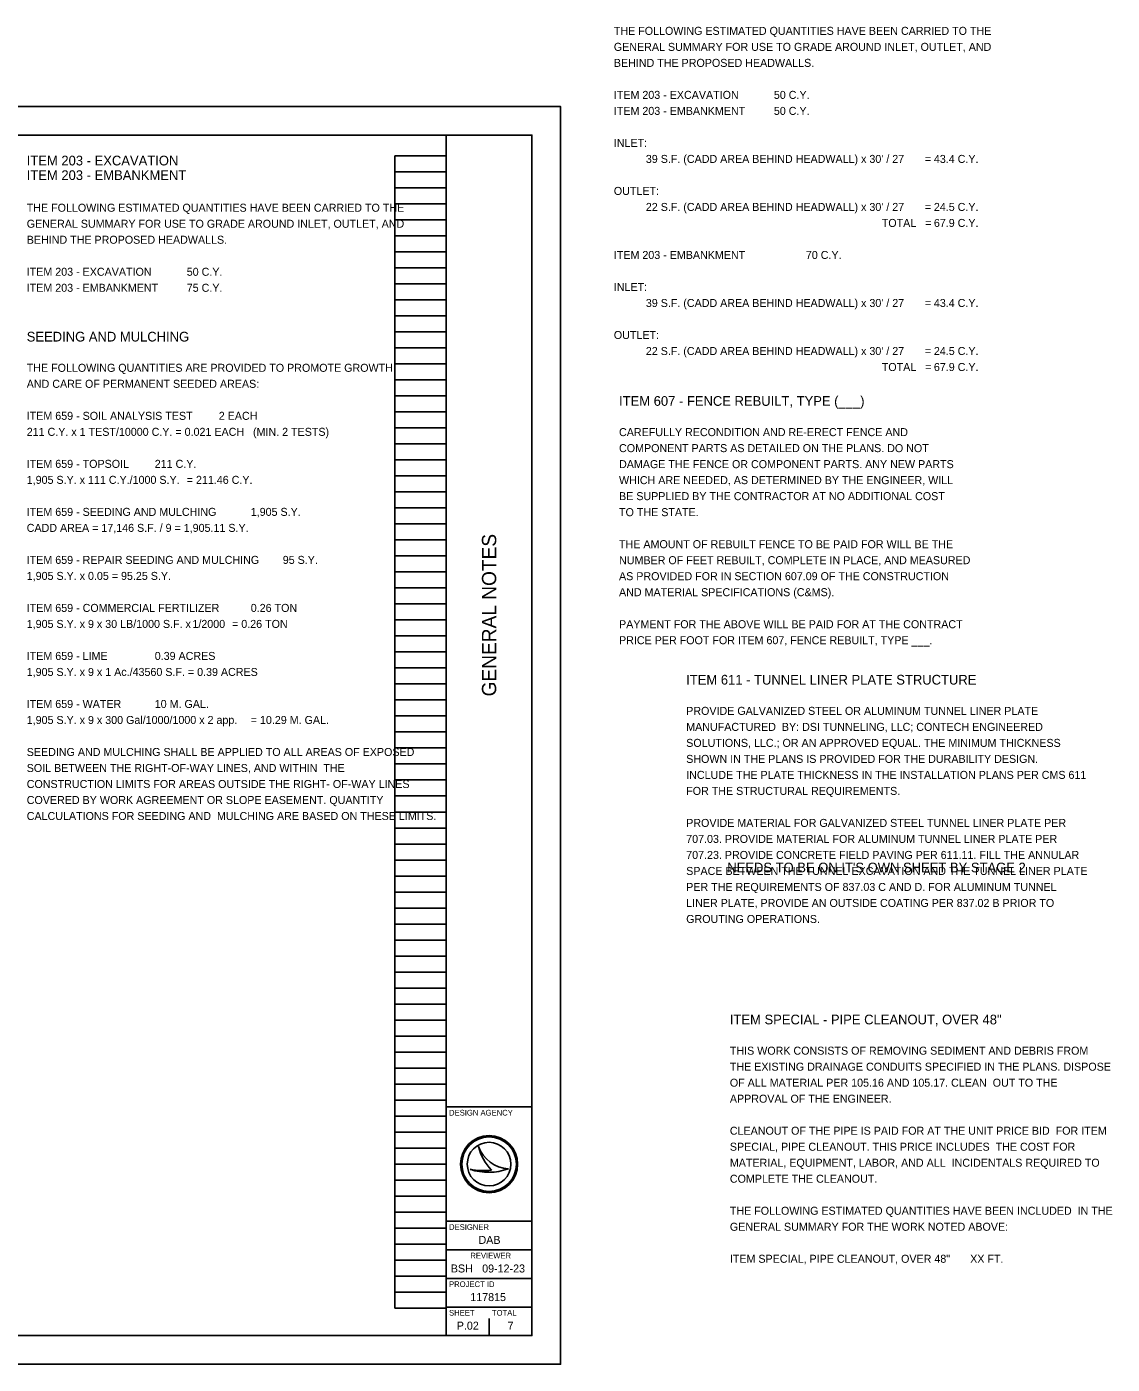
# Model space of a CAD drawing. Extents: x -3.4 to 43.7, y 0 to 26.
# Drawn here: x 24.66 to 43.65, y 0 to 23.4 of the extents above; entities that cross this region are included whole.
import ezdxf

# ---------------------------------------------------------------- set-up
doc = ezdxf.new("R2010")
doc.units = 0
for name, color, linetype in [('SH_Border', 7, 'Continuous'), ('SH_Cut_Line', 7, 'Continuous'), ('SH_Data', 7, 'Continuous'), ('SH_Text', 7, 'Continuous')]:
    doc.layers.add(name, color=color, linetype=linetype)

msp = doc.modelspace()

# ---------------------------------------------------------------- linework, layer by layer
at = {"layer": 'SH_Border'}
for p, q in [((32, 0.5), (32, 21.5)), ((32, 4.5), (33.5, 4.5)), ((32, 2.5), (33.5, 2.5)), ((32, 2), (33.5, 2)), ((32, 1.5), (33.5, 1.5)), ((32, 1), (33.5, 1))]:
    msp.add_line(p, q, dxfattribs=at)
msp.add_lwpolyline([(1.5, 21.5), (33.5, 21.5), (33.5, 0.5), (1.5, 0.5)], close=True, dxfattribs=at)
at = {"layer": 'SH_Cut_Line'}
msp.add_lwpolyline([(0, 0), (34, 0), (34, 22), (0, 22)], close=True, dxfattribs=at)
at = {"layer": 'SH_Data'}
for p, q in [((31.1, 0.98), (31.1, 21.14)), ((31.1, 21.14), (32, 21.14)), ((32, 0.98), (32, 21.14)), ((31.1, 20.86), (32, 20.86)), ((31.1, 20.58), (32, 20.58)), ((31.1, 20.3), (32, 20.3)), ((31.1, 20.02), (32, 20.02)), ((31.1, 19.74), (32, 19.74)), ((31.1, 19.46), (32, 19.46)), ((31.1, 19.18), (32, 19.18)), ((31.1, 18.9), (32, 18.9)), ((31.1, 18.62), (32, 18.62)), ((31.1, 18.34), (32, 18.34)), ((31.1, 18.06), (32, 18.06)), ((31.1, 17.78), (32, 17.78)), ((31.1, 17.5), (32, 17.5)), ((31.1, 17.22), (32, 17.22)), ((31.1, 16.94), (32, 16.94)), ((31.1, 16.66), (32, 16.66)), ((31.1, 16.38), (32, 16.38)), ((31.1, 16.1), (32, 16.1)), ((31.1, 15.82), (32, 15.82)), ((31.1, 15.54), (32, 15.54)), ((31.1, 15.26), (32, 15.26)), ((31.1, 14.98), (32, 14.98)), ((31.1, 14.7), (32, 14.7)), ((31.1, 14.42), (32, 14.42)), ((31.1, 14.14), (32, 14.14)), ((31.1, 13.86), (32, 13.86)), ((31.1, 13.58), (32, 13.58)), ((31.1, 13.3), (32, 13.3)), ((31.1, 13.02), (32, 13.02)), ((31.1, 12.74), (32, 12.74)), ((31.1, 12.46), (32, 12.46)), ((31.1, 12.18), (32, 12.18)), ((31.1, 11.9), (32, 11.9)), ((31.1, 11.62), (32, 11.62)), ((31.1, 11.34), (32, 11.34)), ((31.1, 11.06), (32, 11.06)), ((31.1, 10.78), (32, 10.78)), ((31.1, 10.5), (32, 10.5)), ((31.1, 10.22), (32, 10.22)), ((31.1, 9.94), (32, 9.94)), ((31.1, 9.66), (32, 9.66)), ((31.1, 9.38), (32, 9.38)), ((31.1, 9.1), (32, 9.1)), ((31.1, 8.82), (32, 8.82)), ((31.1, 8.54), (32, 8.54)), ((31.1, 8.26), (32, 8.26)), ((31.1, 7.98), (32, 7.98)), ((31.1, 7.7), (32, 7.7)), ((31.1, 7.42), (32, 7.42)), ((31.1, 7.14), (32, 7.14)), ((31.1, 6.86), (32, 6.86)), ((31.1, 6.58), (32, 6.58)), ((31.1, 6.3), (32, 6.3)), ((31.1, 6.02), (32, 6.02)), ((31.1, 5.74), (32, 5.74)), ((31.1, 5.46), (32, 5.46)), ((31.1, 5.18), (32, 5.18)), ((31.1, 4.9), (32, 4.9)), ((31.1, 4.62), (32, 4.62)), ((31.1, 4.34), (32, 4.34)), ((31.1, 4.06), (32, 4.06)), ((31.1, 3.78), (32, 3.78)), ((32.567, 3.81), (32.567, 3.81)), ((31.1, 3.5), (32, 3.5)), ((32.417, 3.41), (32.417, 3.41)), ((32.75, 3.5), (32.75, 3.5)), ((33.087, 3.419), (33.087, 3.419)), ((31.1, 3.22), (32, 3.22)), ((31.1, 2.94), (32, 2.94)), ((31.1, 2.66), (32, 2.66)), ((31.1, 2.38), (32, 2.38)), ((31.1, 2.1), (32, 2.1)), ((31.1, 1.82), (32, 1.82)), ((31.1, 1.54), (32, 1.54)), ((31.1, 1.26), (32, 1.26)), ((31.1, 0.98), (32, 0.98)), ((32.75, 0.5), (32.75, 0.8)), ((32.375, 0.675), (32.375, 0.675))]:
    msp.add_line(p, q, dxfattribs=at)
for radius in [0.5, 0.477, 0.477, 0.382]:
    msp.add_circle((32.75, 3.5), radius, dxfattribs=at)
for centre, radius, start, end in [((33.116, 3.998), 0.58, 198.9257, 198.9319), ((33.347, 3.97), 0.796, 191.6379, 191.6421), ((33.116, 3.998), 0.58, 198.9319, 267.1657), ((33.347, 3.97), 0.796, 191.6421, 226.0947), ((32.739, 4.37), 1.013, 251.4576, 290.0832), ((32.648, 4.654), 1.266, 259.4964, 259.4995), ((32.739, 4.37), 1.013, 251.4527, 251.4576), ((32.648, 4.654), 1.266, 259.4995, 276.6672)]:
    msp.add_arc(centre, radius, start, end, dxfattribs=at)

# ---------------------------------------------------------------- texts
for s, height, p in [('ITEM 659 - SOIL ANALYSIS TEST', 0.14, (24.66, 16.52)), ('2 EACH', 0.14, (28.02, 16.52)), ('211 C.Y. x 1 TEST/10000 C.Y. = 0.021 EACH   (MIN. 2 TESTS)', 0.14, (24.66, 16.24)), ('ITEM 659 - TOPSOIL', 0.14, (24.66, 15.68)), ('211 C.Y.', 0.14, (26.9, 15.68)), ('1,905 S.Y. x 111 C.Y./1000 S.Y.', 0.14, (24.66, 15.4)), ('= 211.46 C.Y.', 0.14, (27.46, 15.4)), ('ITEM 659 - SEEDING AND MULCHING', 0.14, (24.66, 14.84)), ('1,905 S.Y.', 0.14, (28.58, 14.84)), ('CADD AREA = 17,146 S.F. / 9 = 1,905.11 S.Y.', 0.14, (24.66, 14.56)), ('ITEM 659 - REPAIR SEEDING AND MULCHING', 0.14, (24.66, 14)), ('95 S.Y.', 0.14, (29.14, 14)), ('1,905 S.Y. x 0.05 = 95.25 S.Y.', 0.14, (24.66, 13.72)), ('ITEM 659 - COMMERCIAL FERTILIZER', 0.14, (24.66, 13.16)), ('0.26 TON', 0.14, (28.58, 13.16)), ('1,905 S.Y. x 9 x 30 LB/1000 S.F. x', 0.14, (24.66, 12.88)), ('1/2000 ', 0.14, (27.559, 12.88)), ('= 0.26 TON', 0.14, (28.253, 12.88)), ('ITEM 659 - LIME', 0.14, (24.66, 12.32)), ('0.39 ACRES', 0.14, (26.9, 12.32)), ('1,905 S.Y. x 9 x 1 Ac./43560 S.F. = 0.39 ACRES', 0.14, (24.66, 12.04)), ('ITEM 659 - WATER', 0.14, (24.66, 11.48)), ('10 M. GAL.', 0.14, (26.9, 11.48)), ('1,905 S.Y. x 9 x 300 Gal/1000/1000 x 2 app.', 0.14, (24.66, 11.2)), ('= 10.29 M. GAL.', 0.14, (28.58, 11.2)), ('DESIGN AGENCY', 0.1, (32.05, 4.35)), ('DESIGNER', 0.1, (32.05, 2.35)), ('DAB', 0.14, (32.565, 2.105)), ('REVIEWER', 0.1, (32.422, 1.85)), ('BSH', 0.14, (32.08, 1.605)), ('09-12-23', 0.14, (32.629, 1.605)), ('PROJECT ID', 0.1, (32.05, 1.35)), ('117815', 0.14, (32.421, 1.105)), ('SHEET', 0.1, (32.05, 0.85)), ('TOTAL', 0.1, (32.8, 0.85)), ('P.02', 0.14, (32.185, 0.605)), ('7', 0.14, (33.074, 0.605))]:
    msp.add_text(s, height=height, dxfattribs=at).set_placement(p)
msp.add_text('GENERAL NOTES', height=0.25, rotation=90, dxfattribs=at).set_placement((32.875, 11.682))
at = {"layer": 'SH_Text'}
for s, height, p in [('THE FOLLOWING ESTIMATED QUANTITIES HAVE BEEN CARRIED TO THE ', 0.14, (34.933, 23.254)), ('GENERAL SUMMARY FOR USE TO GRADE AROUND INLET, OUTLET, AND ', 0.14, (34.933, 22.974)), ('BEHIND THE PROPOSED HEADWALLS.', 0.14, (34.933, 22.694)), ('ITEM 203 - EXCAVATION', 0.14, (34.933, 22.134)), ('50 C.Y.', 0.14, (37.733, 22.134)), ('ITEM 203 - EMBANKMENT', 0.14, (34.933, 21.854)), ('50 C.Y.', 0.14, (37.733, 21.854)), ('INLET:', 0.14, (34.933, 21.294)), ('ITEM 203 - EXCAVATION', 0.17, (24.66, 20.97)), ("39 S.F. (CADD AREA BEHIND HEADWALL) x 30' / 27       =", 0.14, (35.493, 21.014)), ('43.4 C.Y.', 0.14, (40.533, 21.014)), ('ITEM 203 - EMBANKMENT', 0.17, (24.66, 20.715)), ('OUTLET:', 0.14, (34.933, 20.454)), ('THE FOLLOWING ESTIMATED QUANTITIES HAVE BEEN CARRIED TO THE ', 0.14, (24.66, 20.16)), ("22 S.F. (CADD AREA BEHIND HEADWALL) x 30' / 27       =", 0.14, (35.493, 20.174)), ('24.5 C.Y. ', 0.14, (40.533, 20.174)), ('GENERAL SUMMARY FOR USE TO GRADE AROUND INLET, OUTLET, AND ', 0.14, (24.66, 19.88)), ('    TOTAL   =', 0.14, (39.413, 19.894)), ('67.9 C.Y.', 0.14, (40.533, 19.894)), ('BEHIND THE PROPOSED HEADWALLS.', 0.14, (24.66, 19.6)), ('ITEM 203 - EMBANKMENT', 0.14, (34.933, 19.334)), ('70 C.Y.', 0.14, (38.293, 19.334)), ('ITEM 203 - EXCAVATION', 0.14, (24.66, 19.04)), ('50 C.Y.', 0.14, (27.46, 19.04)), ('ITEM 203 - EMBANKMENT', 0.14, (24.66, 18.76)), ('75 C.Y.', 0.14, (27.46, 18.76)), ('INLET:', 0.14, (34.933, 18.774)), ("39 S.F. (CADD AREA BEHIND HEADWALL) x 30' / 27       =", 0.14, (35.493, 18.494)), ('43.4 C.Y.', 0.14, (40.533, 18.494)), ('SEEDING AND MULCHING', 0.17, (24.66, 17.89)), ('OUTLET:', 0.14, (34.933, 17.934)), ("22 S.F. (CADD AREA BEHIND HEADWALL) x 30' / 27       =", 0.14, (35.493, 17.654)), ('24.5 C.Y. ', 0.14, (40.533, 17.654)), ('THE FOLLOWING QUANTITIES ARE PROVIDED TO PROMOTE GROWTH ', 0.14, (24.66, 17.36)), ('    TOTAL   =', 0.14, (39.413, 17.374)), ('67.9 C.Y.', 0.14, (40.533, 17.374)), ('AND CARE OF PERMANENT SEEDED AREAS:', 0.14, (24.66, 17.08)), ('ITEM 607 - FENCE REBUILT, TYPE (___)', 0.17, (35.024, 16.765)), ('CAREFULLY RECONDITION AND RE-ERECT FENCE AND', 0.14, (35.024, 16.235)), ('COMPONENT PARTS AS DETAILED ON THE PLANS. DO NOT', 0.14, (35.024, 15.955)), ('DAMAGE THE FENCE OR COMPONENT PARTS. ANY NEW PARTS', 0.14, (35.024, 15.675)), ('WHICH ARE NEEDED, AS DETERMINED BY THE ENGINEER, WILL', 0.14, (35.024, 15.395)), ('BE SUPPLIED BY THE CONTRACTOR AT NO ADDITIONAL COST', 0.14, (35.024, 15.115)), ('TO THE STATE.', 0.14, (35.024, 14.835)), ('THE AMOUNT OF REBUILT FENCE TO BE PAID FOR WILL BE THE', 0.14, (35.024, 14.275)), ('NUMBER OF FEET REBUILT, COMPLETE IN PLACE, AND MEASURED', 0.14, (35.024, 13.995)), ('AS PROVIDED FOR IN SECTION 607.09 OF THE CONSTRUCTION', 0.14, (35.024, 13.715)), ('AND MATERIAL SPECIFICATIONS (C&MS).', 0.14, (35.024, 13.435)), ('PAYMENT FOR THE ABOVE WILL BE PAID FOR AT THE CONTRACT', 0.14, (35.024, 12.875)), ('PRICE PER FOOT FOR ITEM 607, FENCE REBUILT, TYPE ___.', 0.14, (35.024, 12.595)), ('ITEM 611 - TUNNEL LINER PLATE STRUCTURE', 0.17, (36.199, 11.889)), ('PROVIDE GALVANIZED STEEL OR ALUMINUM TUNNEL LINER PLATE ', 0.14, (36.199, 11.359)), ('MANUFACTURED  BY: DSI TUNNELING, LLC; CONTECH ENGINEERED ', 0.14, (36.199, 11.079)), ('SEEDING AND MULCHING SHALL BE APPLIED TO ALL AREAS OF EXPOSED ', 0.14, (24.66, 10.64)), ('SOLUTIONS, LLC.; OR AN APPROVED EQUAL. THE MINIMUM THICKNESS ', 0.14, (36.199, 10.799)), ('SHOWN IN THE PLANS IS PROVIDED FOR THE DURABILITY DESIGN. ', 0.14, (36.199, 10.519)), ('SOIL BETWEEN THE RIGHT-OF-WAY LINES, AND WITHIN  THE ', 0.14, (24.66, 10.36)), ('INCLUDE THE PLATE THICKNESS IN THE INSTALLATION PLANS PER CMS 611 ', 0.14, (36.199, 10.239)), ('CONSTRUCTION LIMITS FOR AREAS OUTSIDE THE RIGHT- OF-WAY LINES ', 0.14, (24.66, 10.08)), ('FOR THE STRUCTURAL REQUIREMENTS. ', 0.14, (36.199, 9.959)), ('COVERED BY WORK AGREEMENT OR SLOPE EASEMENT. QUANTITY ', 0.14, (24.66, 9.8)), ('CALCULATIONS FOR SEEDING AND  MULCHING ARE BASED ON THESE LIMITS.', 0.14, (24.66, 9.52)), ('PROVIDE MATERIAL FOR GALVANIZED STEEL TUNNEL LINER PLATE PER ', 0.14, (36.199, 9.399)), ('707.03. PROVIDE MATERIAL FOR ALUMINUM TUNNEL LINER PLATE PER ', 0.14, (36.199, 9.119)), ('707.23. PROVIDE CONCRETE FIELD PAVING PER 611.11. FILL THE ANNULAR', 0.14, (36.199, 8.839)), ('SPACE BETWEEN THE TUNNEL EXCAVATION AND THE TUNNEL LINER PLATE ', 0.14, (36.199, 8.559)), ("NEEDS TO BE ON IT'S OWN SHEET BY STAGE 2", 0.17, (36.918, 8.604)), ('PER THE REQUIREMENTS OF 837.03 C AND D. FOR ALUMINUM TUNNEL ', 0.14, (36.199, 8.279)), ('LINER PLATE, PROVIDE AN OUTSIDE COATING PER 837.02 B PRIOR TO ', 0.14, (36.199, 7.999)), ('GROUTING OPERATIONS. ', 0.14, (36.199, 7.719)), ('ITEM SPECIAL - PIPE CLEANOUT, OVER 48"', 0.17, (36.963, 5.945)), ('THIS WORK CONSISTS OF REMOVING SEDIMENT AND DEBRIS FROM ', 0.14, (36.963, 5.415)), ('THE EXISTING DRAINAGE CONDUITS SPECIFIED IN THE PLANS. DISPOSE ', 0.14, (36.963, 5.135)), ('OF ALL MATERIAL PER 105.16 AND 105.17. CLEAN  OUT TO THE ', 0.14, (36.963, 4.855)), ('APPROVAL OF THE ENGINEER.', 0.14, (36.963, 4.575)), ('CLEANOUT OF THE PIPE IS PAID FOR AT THE UNIT PRICE BID  FOR ITEM ', 0.14, (36.963, 4.015)), ('SPECIAL, PIPE CLEANOUT. THIS PRICE INCLUDES  THE COST FOR ', 0.14, (36.963, 3.735)), ('MATERIAL, EQUIPMENT, LABOR, AND ALL  INCIDENTALS REQUIRED TO ', 0.14, (36.963, 3.455)), ('COMPLETE THE CLEANOUT.', 0.14, (36.963, 3.175)), ('THE FOLLOWING ESTIMATED QUANTITIES HAVE BEEN INCLUDED  IN THE ', 0.14, (36.963, 2.615)), ('GENERAL SUMMARY FOR THE WORK NOTED ABOVE:', 0.14, (36.963, 2.335)), ('ITEM SPECIAL, PIPE CLEANOUT, OVER 48"        ', 0.14, (36.963, 1.775)), ('  XX FT.', 0.14, (41.064, 1.775))]:
    msp.add_text(s, height=height, dxfattribs=at).set_placement(p)

doc.saveas('drawing.dxf')
